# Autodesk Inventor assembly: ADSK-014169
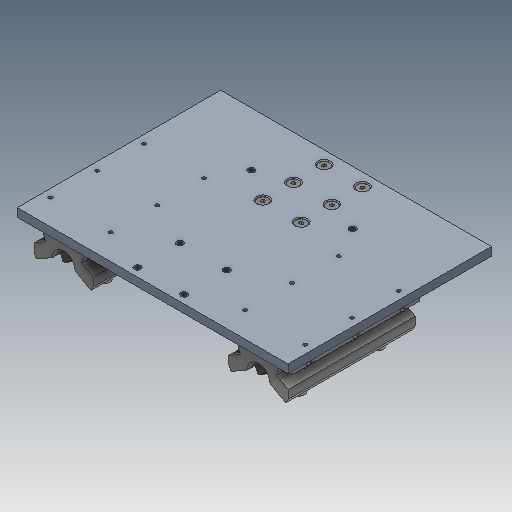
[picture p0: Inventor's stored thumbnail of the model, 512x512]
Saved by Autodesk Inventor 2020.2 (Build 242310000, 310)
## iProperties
Created: 2019-10
Part Number: ADSK-014169
Document SubType Name: Assembly
Designer: lutzd
Mass: 8570.32 g
Surface Area: 5886.55 cm^2
Volume: 3102.23 cm^3
Density: 2.76263 g/cm^3
VLDS_Profile: Default Assembly
VLDS_TimeStamp: 2016-07-29
VLDS_FailCnt: 0
VLDS_AcceptCnt: 0
Dimensions: 77,6x310x406 mm
Mass: 8,57 kg
DocNumber: ADSK-014169
Folder: 01 - Themengebiete\Simplification\01 - Packaging machine\
VDS_Category: 3D Komponenten
VDS_NumSchm: Autodesk
Title: carriage
Author: lutzd
Revision Number: -
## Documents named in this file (12)
- D:\07 - DEMODATEN\OTX 2019 - Dataset - UPDATE - Dez2019\Designs\07-Packing machine\ADSK-014169.iam
- D:\07 - DEMODATEN\OTX 2019 - Dataset - UPDATE - Dez2019\Designs\07-Packing machine\500166.iam
- D:\07 - DEMODATEN\OTX 2019 - Dataset - UPDATE - Dez2019\Designs\07-Packing machine\Parts\ADSK-011763.ipt
- D:\07 - DEMODATEN\OTX 2019 - Dataset - UPDATE - Dez2019\Content Center Files\de-DE\DIN 9021\DIN 9021 - 4,3.ipt
- D:\07 - DEMODATEN\OTX 2019 - Dataset - UPDATE - Dez2019\Content Center Files\de-DE\ISO 4762(2)\ISO 4762 - M4 x 20ISO.ipt
- D:\07 - DEMODATEN\OTX 2019 - Dataset - UPDATE - Dez2019\Designs\07-Packing machine\Parts\ADSK-011356.ipt
- D:\07 - DEMODATEN\OTX 2019 - Dataset - UPDATE - Dez2019\Designs\07-Packing machine\Parts\ADSK-011759.ipt
- D:\07 - DEMODATEN\OTX 2019 - Dataset - UPDATE - Dez2019\Content Center Files\de-DE\ISO 4762(2)\ISO 4762 - M8 x 16ISO.ipt
- D:\07 - DEMODATEN\OTX 2019 - Dataset - UPDATE - Dez2019\Designs\07-Packing machine\Parts\ADSK-011358.ipt
- D:\07 - DEMODATEN\OTX 2019 - Dataset - UPDATE - Dez2019\Content Center Files\de-DE\ISO 10642(1)\ISO 10642 - M8x20.ipt
- D:\07 - DEMODATEN\OTX 2019 - Dataset - UPDATE - Dez2019\Content Center Files\de-DE\ISO 10642(1)\ISO 10642 - M8x25.ipt
- D:\07 - DEMODATEN\OTX 2019 - Dataset - UPDATE - Dez2019\Designs\07-Packing machine\Parts\ADSK-011374.ipt
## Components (50 placed, 11 different names)
1. 500166:1 [sub-assembly] — Passend:37, Passend:38, Passend:39, Passend:40, Passend:41, Passend:42, Passend:43, Passend:44, Passend:45, Passend:46, Passend:47, Passend:48, Passend:49, Passend:50, Passend:51, Passend:52, Passend:53, Passend:54, Passend:80, Passend:81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
2. ADSK-011763:1 — Passend:38, Passend:39, Passend:42, Passend:61, Passend:62, Passend:63, Passend:64, Passend:65, Passend:66
3. ADSK-011763:2 — Passend:37, Passend:40, Passend:41, Passend:55, Passend:56, Passend:57, Passend:58, Passend:59, Passend:60
4. ADSK-011374:1 — Passend:81, Passend:84
5. ADSK-011374:2 — Passend:80, Passend:82, Passend:83
6. ADSK-011356:1
7. ADSK-011759:1
8. ISO 4762 M8 x 16:1
9. ISO 4762 M8 x 16:2
10. ISO 4762 M8 x 16:3
11. ISO 4762 M8 x 16:4
12. ISO 4762 M8 x 16:5
13. ISO 4762 M8 x 16:6
14. ISO 4762 M8 x 16:7
15. ISO 4762 M8 x 16:8
16. ADSK-011358:1
17. ISO 10642 M8x20:1
18. ISO 10642 M8x20:2 — Passend:82
19. ISO 10642 M8x20:3
20. ISO 10642 M8x20:4
21. ISO 10642 M8x25:1 — Passend:85
22. ISO 10642 M8x25:2 — Passend:86
23. ISO 10642 M8x25:3 — Passend:88
24. ISO 10642 M8x25:4 — Passend:89
25. ISO 10642 M8x25:5 — Passend:87
26. ISO 10642 M8x25:6 — Passend:90
27. DIN 9021 4,3:1 — Passend:61
28. ISO 4762 M4 x 20:1 — Passend:46
29. DIN 9021 4,3:2 — Passend:62
30. ISO 4762 M4 x 20:2 — Passend:47
31. DIN 9021 4,3:3 — Passend:63
32. ISO 4762 M4 x 20:3 — Passend:48
33. DIN 9021 4,3:4 — Passend:66
34. ISO 4762 M4 x 20:4 — Passend:45
35. DIN 9021 4,3:5 — Passend:65
36. ISO 4762 M4 x 20:5 — Passend:44
37. DIN 9021 4,3:6 — Passend:64
38. ISO 4762 M4 x 20:6 — Passend:43
39. DIN 9021 4,3:7 — Passend:56
40. ISO 4762 M4 x 20:7 — Passend:53
41. DIN 9021 4,3:8 — Passend:60
42. ISO 4762 M4 x 20:8 — Passend:51
43. DIN 9021 4,3:9 — Passend:59
44. ISO 4762 M4 x 20:9 — Passend:50
45. DIN 9021 4,3:10 — Passend:55
46. ISO 4762 M4 x 20:10 — Passend:54
47. DIN 9021 4,3:11 — Passend:57
48. ISO 4762 M4 x 20:11 — Passend:52
49. DIN 9021 4,3:12 — Passend:58
50. ISO 4762 M4 x 20:12 — Passend:49
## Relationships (41: Mate 41)
- Passend:37 [Mate]: 500166:1 ↔ ADSK-011763:2
- Passend:38 [Mate]: 500166:1 ↔ ADSK-011763:1
- Passend:39 [Mate]: 500166:1 ↔ ADSK-011763:1
- Passend:40 [Mate]: 500166:1 ↔ ADSK-011763:2
- Passend:41 [Mate]: 500166:1 ↔ ADSK-011763:2
- Passend:42 [Mate]: 500166:1 ↔ ADSK-011763:1
- Passend:43 [Mate]: 500166:1 ↔ ISO 4762 M4 x 20:6
- Passend:44 [Mate]: 500166:1 ↔ ISO 4762 M4 x 20:5
- Passend:45 [Mate]: 500166:1 ↔ ISO 4762 M4 x 20:4
- Passend:46 [Mate]: 500166:1 ↔ ISO 4762 M4 x 20:1
- Passend:47 [Mate]: 500166:1 ↔ ISO 4762 M4 x 20:2
- Passend:48 [Mate]: 500166:1 ↔ ISO 4762 M4 x 20:3
- Passend:49 [Mate]: 500166:1 ↔ ISO 4762 M4 x 20:12
- Passend:50 [Mate]: 500166:1 ↔ ISO 4762 M4 x 20:9
- Passend:51 [Mate]: 500166:1 ↔ ISO 4762 M4 x 20:8
- Passend:52 [Mate]: 500166:1 ↔ ISO 4762 M4 x 20:11
- Passend:53 [Mate]: 500166:1 ↔ ISO 4762 M4 x 20:7
- Passend:54 [Mate]: 500166:1 ↔ ISO 4762 M4 x 20:10
- Passend:55 [Mate]: ADSK-011763:2 ↔ DIN 9021 4,3:10
- Passend:56 [Mate]: ADSK-011763:2 ↔ DIN 9021 4,3:7
- Passend:57 [Mate]: ADSK-011763:2 ↔ DIN 9021 4,3:11
- Passend:58 [Mate]: ADSK-011763:2 ↔ DIN 9021 4,3:12
- Passend:59 [Mate]: ADSK-011763:2 ↔ DIN 9021 4,3:9
- Passend:60 [Mate]: ADSK-011763:2 ↔ DIN 9021 4,3:8
- Passend:61 [Mate]: ADSK-011763:1 ↔ DIN 9021 4,3:1
- Passend:62 [Mate]: ADSK-011763:1 ↔ DIN 9021 4,3:2
- Passend:63 [Mate]: ADSK-011763:1 ↔ DIN 9021 4,3:3
- Passend:64 [Mate]: ADSK-011763:1 ↔ DIN 9021 4,3:6
- Passend:65 [Mate]: ADSK-011763:1 ↔ DIN 9021 4,3:5
- Passend:66 [Mate]: ADSK-011763:1 ↔ DIN 9021 4,3:4
- Passend:80 [Mate]: 500166:1 ↔ ADSK-011374:2
- Passend:81 [Mate]: 500166:1 ↔ ADSK-011374:1
- Passend:82 [Mate]: ADSK-011374:2 ↔ ISO 10642 M8x20:2
- Passend:83 [Mate]: 500166:1 ↔ ADSK-011374:2
- Passend:84 [Mate]: 500166:1 ↔ ADSK-011374:1
- Passend:85 [Mate]: 500166:1 ↔ ISO 10642 M8x25:1
- Passend:86 [Mate]: 500166:1 ↔ ISO 10642 M8x25:2
- Passend:87 [Mate]: 500166:1 ↔ ISO 10642 M8x25:5
- Passend:88 [Mate]: 500166:1 ↔ ISO 10642 M8x25:3
- Passend:89 [Mate]: 500166:1 ↔ ISO 10642 M8x25:4
- Passend:90 [Mate]: 500166:1 ↔ ISO 10642 M8x25:6
## Named parameters: d57_d48 = 0, d58_d49 = 0, d59_d48 = 0, d60_d49 = 0, d61_d48 = 0, d62_d49 = 0, d63_d48 = 0, d64_d49 = 0, d65_d48 = 0, d66_d49 = 0, d67_d48 = 0, d68_d49 = 0, d18_d78 = 0, d19_d79 = 0, d20_d80 = 0, d21_d81 = 0, d22_d82 = 0, d23_d83 = 0, d24_d57_d48 = 0, d25_d58_d49 = 0, d26_d59_d48 = 0, d27_d60_d49 = 0, d28_d61_d48 = 0, d29_d62_d49 = 0, d30_d63_d48 = 0, d31_d64_d49 = 0, d32_d65_d48 = 0, d33_d66_d49 = 0, d34_d67_d48 = 0, d35_d68_d49 = 0
